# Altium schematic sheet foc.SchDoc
size A3; SheetNumber: 1; SheetTotal: 1
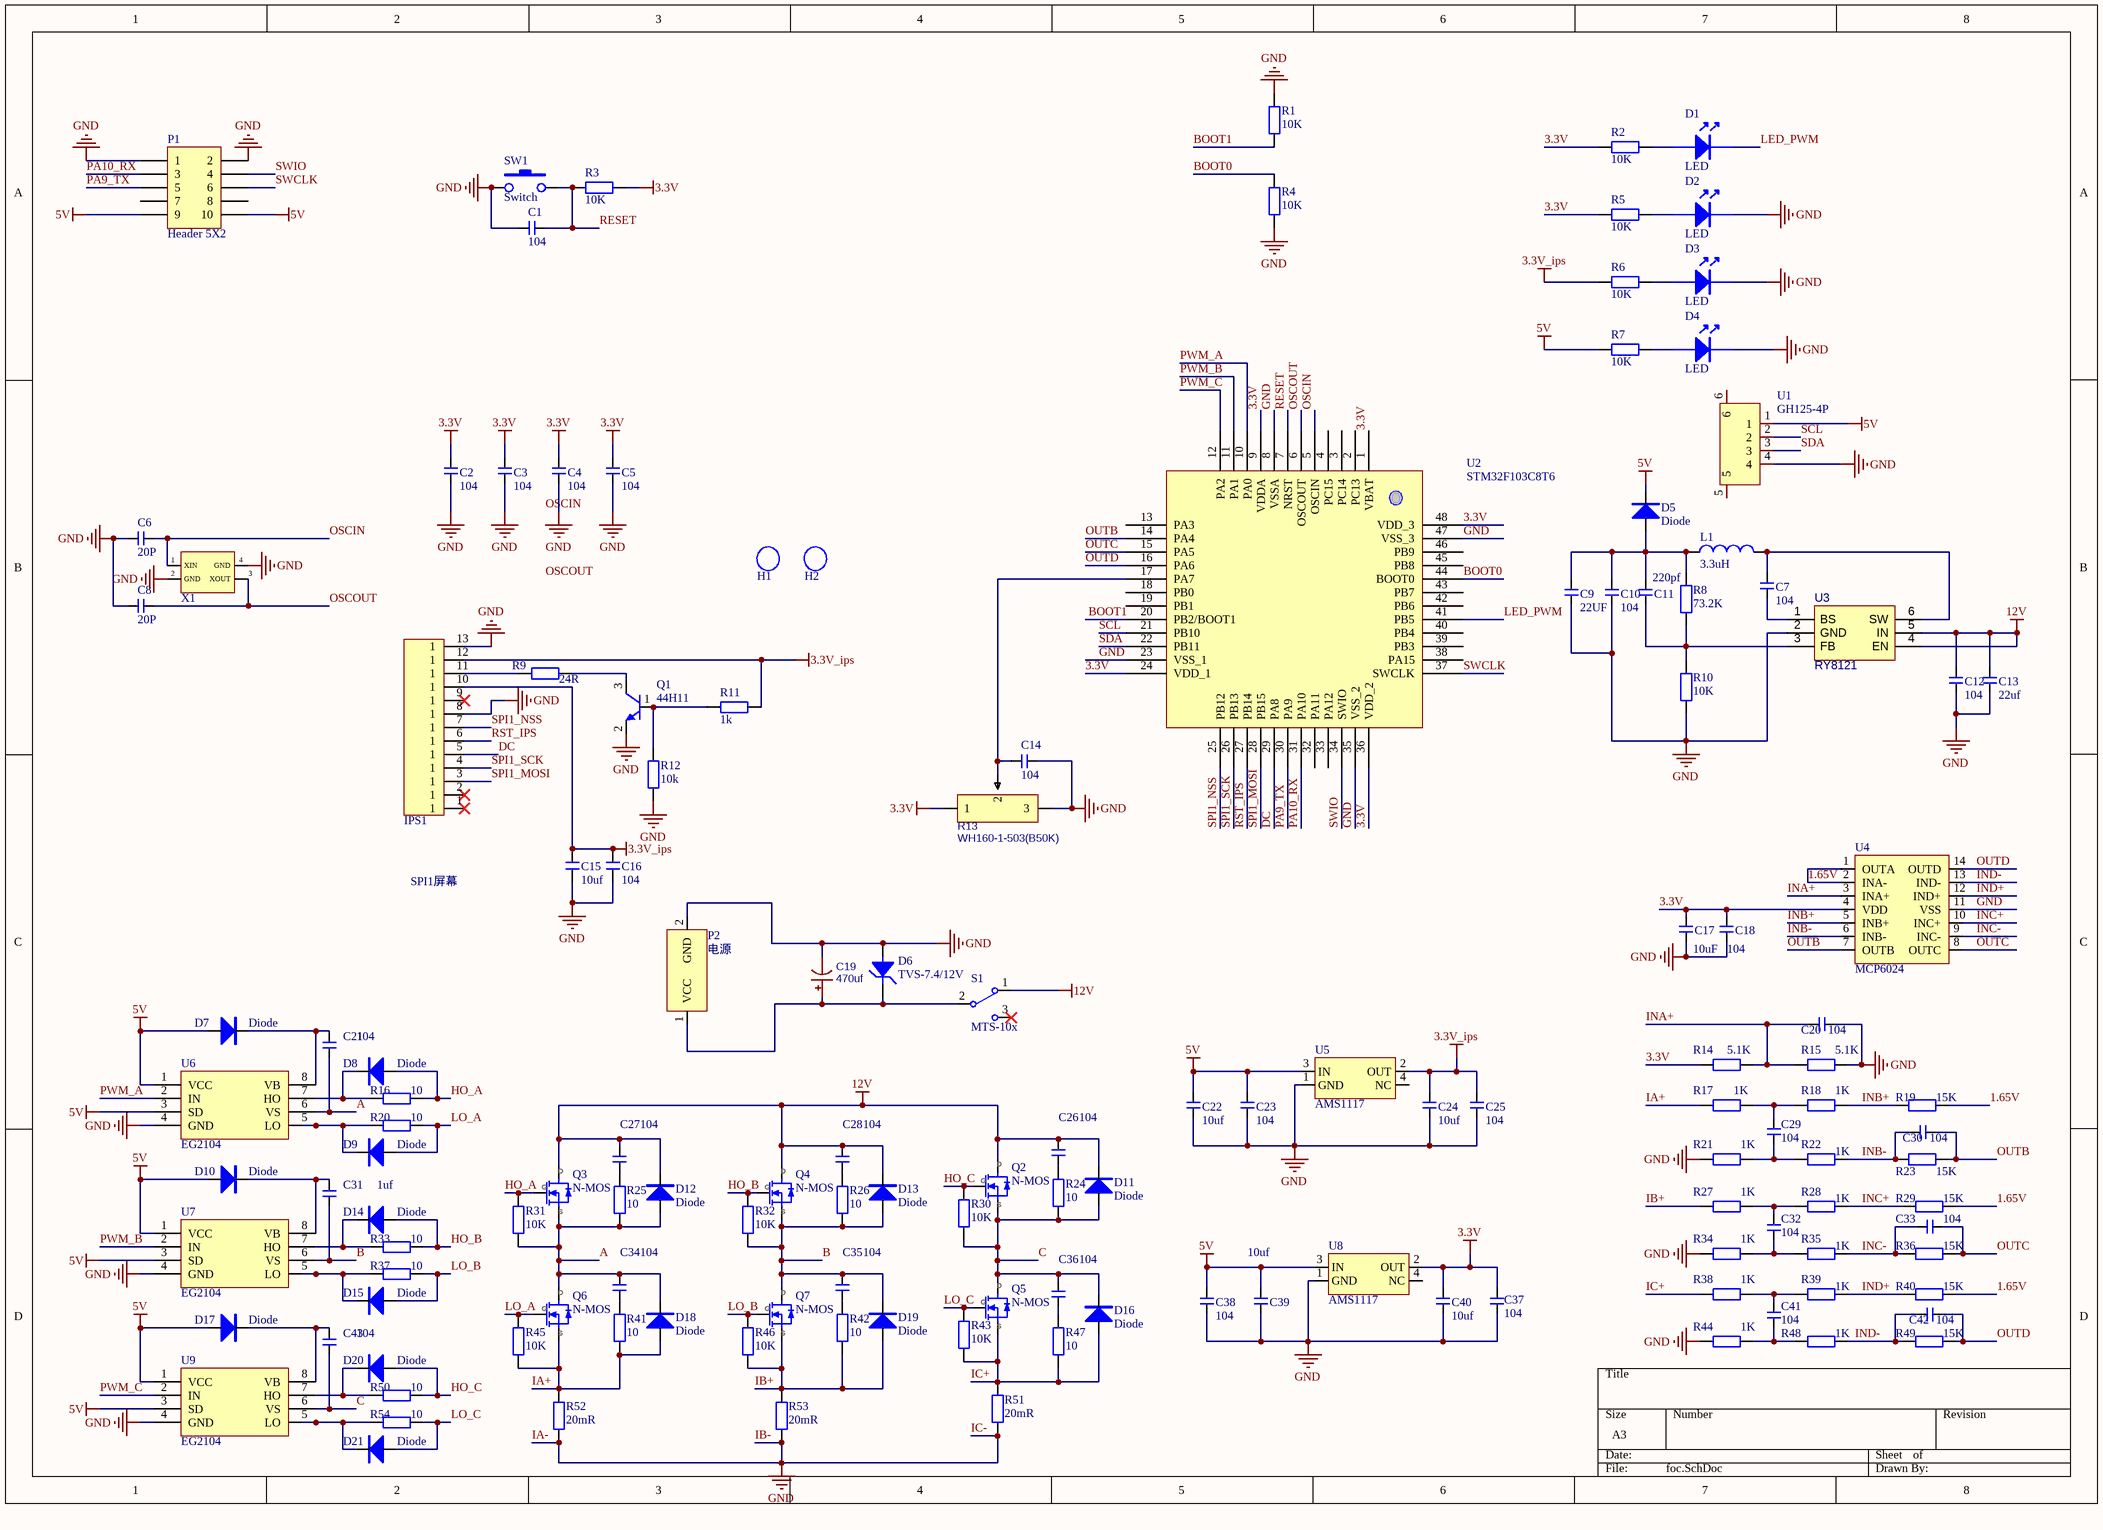
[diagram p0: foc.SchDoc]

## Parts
C1  104  [C0603]
C2  104  [C0603]
C3  104  [C0603]
C4  104  [C0603]
C5  104  [C0603]
C6  20P  [C0603]
C7  104  [C0603]
C8  20P  [C0603]
C9  22UF  [C0603]
C10  104  [C0603]
C11  220pf  [C0603]
C12  104  [C0603]
C13  22uf  [C0603]
C14  104  [C0603]
C15  10uf  [C0603]
C16  104  [C0603]
C17  10uF  [C0603]
C18  104  [C0603]
C19  470uf  [CAP-SMD_BD6.3-L6.6-W6.6-LS7.2-R-RD]
C20  104  [C0603]
C21  104  [C0603]
C22  10uf  [C0603]
C23  104  [C0603]
C24  10uf  [C0603]
C25  104  [C0603]
C26  104  [C0603]
C27  104  [C0603]
C28  104  [C0603]
C29  104  [C0603]
C30  104  [C0603]
C31  1uf  [C0603]
C32  104  [C0603]
C33  104  [C0603]
C34  104  [C0603]
C35  104  [C0603]
C36  104  [C0603]
C37  104  [C0603]
C38  104  [C0603]
C39  10uf  [C0603]
C40  10uf  [C0603]
C41  104  [C0603]
C42  104  [C0603]
C43  104  [C0603]
D1  LED  [LED0603]
D2  LED  [LED0603]
D3  LED  [LED0603]
D4  LED  [LED0603]
D5  Diode  [SOD-123FL_L2.7-W1.8-LS3.8-RD]
D6  TVS-7.4/12V  [SMA]
D7  Diode  [SOD-123FL_L2.7-W1.8-LS3.8-RD]
D8  Diode  [ESC_L1.2-W0.8-LS1.6-RD]
D9  Diode  [ESC_L1.2-W0.8-LS1.6-RD]
D10  Diode  [SOD-123FL_L2.7-W1.8-LS3.8-RD]
D11  Diode  [SOD-123FL_L2.7-W1.8-LS3.8-RD]
D12  Diode  [SOD-123FL_L2.7-W1.8-LS3.8-RD]
D13  Diode  [SOD-123FL_L2.7-W1.8-LS3.8-RD]
D14  Diode  [ESC_L1.2-W0.8-LS1.6-RD]
D15  Diode  [ESC_L1.2-W0.8-LS1.6-RD]
D16  Diode  [SOD-123FL_L2.7-W1.8-LS3.8-RD]
D17  Diode  [SOD-123FL_L2.7-W1.8-LS3.8-RD]
D18  Diode  [SOD-123FL_L2.7-W1.8-LS3.8-RD]
D19  Diode  [SOD-123FL_L2.7-W1.8-LS3.8-RD]
D20  Diode  [ESC_L1.2-W0.8-LS1.6-RD]
D21  Diode  [ESC_L1.2-W0.8-LS1.6-RD]
H1  Hole  [铜柱孔3]  (value not drawn)
H2  Hole  [铜柱孔3]  (value not drawn)
IPS1  IPS1.14  [IPS]  (value not drawn)
L1  3.3uH  [0402 TPC 4*4*2]
P1  Header 5X2  [HDR2X5]
P2  电源  [POWER]
Q1  44H11  [SOT-23-3_L2.9-W1.3-P1.90-LS2.4-BR]
Q2  N-MOS  [TDSON-8]
Q3  N-MOS  [TDSON-8]
Q4  N-MOS  [TDSON-8]
Q5  N-MOS  [TDSON-8]
Q6  N-MOS  [TDSON-8]
Q7  N-MOS  [TDSON-8]
R1  10K  [R0603]
R2  10K  [R0603]
R3  10K  [R0603]
R4  10K  [R0603]
R5  10K  [R0603]
R6  10K  [R0603]
R7  10K  [R0603]
R8  73.2K  [R0603]
R9  24R  [R0603]
R10  10K  [R0603]
R11  1k  [R0603]
R12  10k  [R0603]
R13  WH160-1-503(B50K)  [滑动变阻器]
R14  5.1K  [R0603]
R15  5.1K  [R0603]
R16  10  [R0603]
R17  1K  [R0603]
R18  1K  [R0603]
R19  15K  [R0603]
R20  10  [R0603]
R21  1K  [R0603]
R22  1K  [R0603]
R23  15K  [R0603]
R24  10  [R0603]
R25  10  [R0603]
R26  10  [R0603]
R27  1K  [R0603]
R28  1K  [R0603]
R29  15K  [R0603]
R30  10K  [R0603]
R31  10K  [R0603]
R32  10K  [R0603]
R33  10  [R0603]
R34  1K  [R0603]
R35  1K  [R0603]
R36  15K  [R0603]
R37  10  [R0603]
R38  1K  [R0603]
R39  1K  [R0603]
R40  15K  [R0603]
R41  10  [R0603]
R42  10  [R0603]
R43  10K  [R0603]
R44  1K  [R0603]
R45  10K  [R0603]
R46  10K  [R0603]
R47  10  [R0603]
R48  1K  [R0603]
R49  15K  [R0603]
R50  10  [R0603]
R51  20mR  [R1206]
R52  20mR  [R1206]
R53  20mR  [R1206]
R54  10  [R0603]
S1  MTS-10x  [SW-TH_HOOYA_SS-12D10G4]
SW1  Switch  [SW-SMD_L4.0-W2.9-LS5.0]
U1  GH125-4P  [CONN-SMD_4P-P1.27_GH125-S04DCA-00]
U2  STM32F103C8T6  [48P]
U3  RY8121  [SOT-23-6]
U4  MCP6024  [SOP14_L]
U5  AMS1117  [SOT-89_L4.5-W2.5-P1.50-LS4.2-BR]
U6  EG2104  [SOP-8]
U7  EG2104  [SOP-8]
U8  AMS1117  [SOT-89_L4.5-W2.5-P1.50-LS4.2-BR]
U9  EG2104  [SOP-8]
X1  XTAL-4  [OSC-SMD_4P-L3.2-W2.5-BL]  (value not drawn)

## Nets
3.3V: C2.2 C3.2 C4.2 C5.2 C17.1 C18.1 C37.2 C40.2 R2.1 R3.1 R5.1 R13.1 R14.2 U2.1(VBAT) U2.9(VDDA) U2.24(VDD_1) U2.36(VDD_2) U2.48(VDD_3) U4.4(VDD) U8.2(OUT)
3.3V_ips: C15.2 C16.2 C24.2 C25.2 IPS1.10(1) IPS1.12(1) R6.1 R11.1 U5.2(OUT)
5V: C22.2 C23.2 C38.2 C39.2 D5.1 D7.2 D10.2 D17.2 P1.9 P1.10 R7.1 U1.1 U5.3(IN) U6.1(VCC) U6.3(SD) U7.1(VCC) U7.3(SD) U8.3(IN) U9.1(VCC) U9.3(SD)
12V: C12.2 C13.2 C26.2 C27.2 C28.2 D11.1 D12.1 D13.1 Q2.1(D) Q3.1(D) Q4.1(D) S1.1 U3.4(EN) U3.5(IN)
GND: C1.2 C2.1 C3.1 C4.1 C5.1 C6.2 C8.2 C9.1 C10.1 C12.1 C13.1 C14.1 C15.1 C16.1 C17.2 C18.2 C19.2 C20.1 C22.1 C23.1 C24.1 C25.1 C37.1 C38.1 C39.1 C40.1 D2.N D3.N D4.N D6.A IPS1.8(1) IPS1.13(1) P1.1 P1.2 P2.2(GND) Q1.2(E) R1.1 R4.2 R10.1 R12.2 R13.3 R15.1 R21.2 R34.2 R44.2 R51.1 R52.1 R53.1 SW1.1 U1.4 U2.8(VSSA) U2.23(VSS_1) U2.35(VSS_2) U2.47(VSS_3) U3.2(GND) U4.11(VSS) U5.1(GND) U6.4(GND) U7.4(GND) U8.1(GND) U9.4(GND) X1.2(GND) X1.4(GND)  [also labelled IA-, IB-, IC-]
1.65V: R19.1 R29.1 R40.1 U4.1(OUTA) U4.2(INA-)
A: C21.1 C34.2 D12.2 D18.1 Q3.3(S) Q6.1(D) R25.2 R31.1 U6.6(VS)
B: C31.1 C35.2 D13.2 D19.1 Q4.3(S) Q7.1(D) R26.2 R32.1 U7.6(VS)
BOOT0: R4.1 U2.44(BOOT0)
BOOT1: R1.2 U2.20(PB2/BOOT1)
C: C36.2 C43.1 D11.2 D16.1 Q2.3(S) Q5.1(D) R24.2 R30.1 U9.6(VS)
DC: IPS1.5(1) U2.29(PA8)
HO_A: D8.2 Q3.2(G) R16.1 R31.2
HO_B: D14.2 Q4.2(G) R32.2 R33.1
HO_C: D20.2 Q2.2(G) R30.2 R50.1
IA+: D18.2 Q6.3(S) R17.2 R41.2 R45.1 R52.2
IB+: D19.2 Q7.3(S) R27.2 R42.2 R46.1 R53.2
IC+: D16.2 Q5.3(S) R38.2 R43.1 R47.2 R51.2
INA+: C20.2 R14.1 R15.2 U4.3(INA+)
INB+: R18.1 R19.2 U4.5(INB+)
INB-: C30.2 R22.1 R23.2 U4.6(INB-)
INC+: R28.1 R29.2 U4.10(INC+)
INC-: C33.2 R35.1 R36.2 U4.9(INC-)
IND+: R39.1 R40.2 U4.12(IND+)
IND-: C42.2 R48.1 R49.2 U4.13(IND-)
LED_PWM: D1.N U2.41(PB5)
LO_A: D9.2 Q6.2(G) R20.1 R45.2
LO_B: D15.2 Q7.2(G) R37.1 R46.2
LO_C: D21.2 Q5.2(G) R43.2 R54.1
OSCIN: C6.1 U2.5(OSCIN) X1.1(XIN)
OSCOUT: C8.1 U2.6(OSCOUT) X1.3(XOUT)
OUTB: C30.1 R23.1 U2.14(PA4) U4.7(OUTB)
OUTC: C33.1 R36.1 U2.15(PA5) U4.8(OUTC)
OUTD: C42.1 R49.1 U2.16(PA6) U4.14(OUTD)
PA9_TX: P1.5 U2.30(PA9)
PA10_RX: P1.3 U2.31(PA10)
PWM_A: U2.10(PA0) U6.2(IN)
PWM_B: U2.11(PA1) U7.2(IN)
PWM_C: U2.12(PA2) U9.2(IN)
RESET: C1.1 R3.2 SW1.2 U2.7(NRST)
RST_IPS: IPS1.6(1) U2.27(PB14)
SCL: U1.2 U2.21(PB10)
SDA: U1.3 U2.22(PB11)
SPI1_MOSI: IPS1.3(1) U2.28(PB15)
SPI1_NSS: IPS1.7(1) U2.25(PB12)
SPI1_SCK: IPS1.4(1) U2.26(PB13)
SWCLK: P1.6 U2.37(SWCLK)
SWIO: P1.4 U2.34(SWIO)
NetC7_1: C7.1 U3.1(BS)
NetC7_2: C7.2 L1.2 U3.6(SW)
NetC9_2: C9.2 C10.2 C11.2 D5.2 L1.1 R8.2
NetC11_1: C11.1 R8.1 R10.2 U3.3(FB)
NetC14_2: C14.2 R13.2 U2.17(PA7)
NetC19_1: C19.1 D6.N P2.1(VCC) S1.2
NetC21_2: C21.2 D7.1 U6.8(VB)
NetC26_1: C26.1 R24.1
NetC27_1: C27.1 R25.1
NetC28_1: C28.1 R26.1
NetC29_1: C29.1 R17.1 R18.2
NetC29_2: C29.2 R21.1 R22.2
NetC31_2: C31.2 D10.1 U7.8(VB)
NetC32_1: C32.1 R34.1 R35.2
NetC32_2: C32.2 R27.1 R28.2
NetC34_1: C34.1 R41.1
NetC35_1: C35.1 R42.1
NetC36_1: C36.1 R47.1
NetC41_1: C41.1 R44.1 R48.2
NetC41_2: C41.2 R38.1 R39.2
NetC43_2: C43.2 D17.1 U9.8(VB)
NetD1_A: D1.A R2.2
NetD2_A: D2.A R5.2
NetD3_A: D3.A R6.2
NetD4_A: D4.A R7.2
NetD8_1: D8.1 R16.2 U6.7(HO)
NetD9_1: D9.1 R20.2 U6.5(LO)
NetD14_1: D14.1 R33.2 U7.7(HO)
NetD15_1: D15.1 R37.2 U7.5(LO)
NetD20_1: D20.1 R50.2 U9.7(HO)
NetD21_1: D21.1 R54.2 U9.5(LO)
NetIPS1_11: IPS1.11(1) R9.2
NetQ1_1: Q1.1(B) R11.2 R12.1
NetQ1_3: Q1.3(C) R9.1

Not connected (* = marked no-connect by the designer): IPS1 1* 2(1)* 9(1)*; P1 7 8; S1 3*; U1 5 6; U2 2(PC13) 3(PC14) 4(PC15) 13(PA3) 18(PB0) 19(PB1) 32(PA11) 33(PA12) 38(PA15) 39(PB3) 40(PB4) 42(PB6) 43(PB7) 45(PB8) 46(PB9); U5 4(NC); U8 4(NC)

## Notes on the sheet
- SPI1屏幕
- Labels drawn without touching a wire or pin: OSCIN, OSCOUT

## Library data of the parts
C1-C18 C20-C43 = C: 无极性电容; BOM名称: 无极性贴片电容; 版权归属: 源创客
C19 = CAP+: 电解电容 10uf  贴片型 钽电容的正极是实物有线的一段; BOM_Manufacturer: ROQANG; BOM_Manufacturer Part: RVT1V100M0405; nameAlias: Capacitance
D5 D7-D21 = 二极管: Diode 1N series
H1 H2 = Hole: 电机的洞
L1 = L: 电感; BOM名称: 小功率贴片电感; 版权归属: 源创客
P1 = Header 5X2: Header, 5-Pin, Dual row
P2 = power
Q1 = NPN: NPN型; BOM名称: 互补功率-NPN型; 版权归属: 源创客; 属性: 80V 8A 50W
Q2-Q7 = N-MOS: N沟场效应管; 版权归属: 源创客
R1-R12 R14-R54 = R: 电阻; BOM名称: 贴片电阻; 版权归属: 源创客
R13 = WH160-1-503(B50K): 拨码开关; Manufacturer: JML; nameAlias: Value
S1 = MTS-10x: MTS10x系列3脚扭子开关; 版权归属: 源创客
U3 = RY8121: 18V 2A 1MHz Synchronous Step-Down Regulator
X1 = XTAL-4: 贴片晶振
